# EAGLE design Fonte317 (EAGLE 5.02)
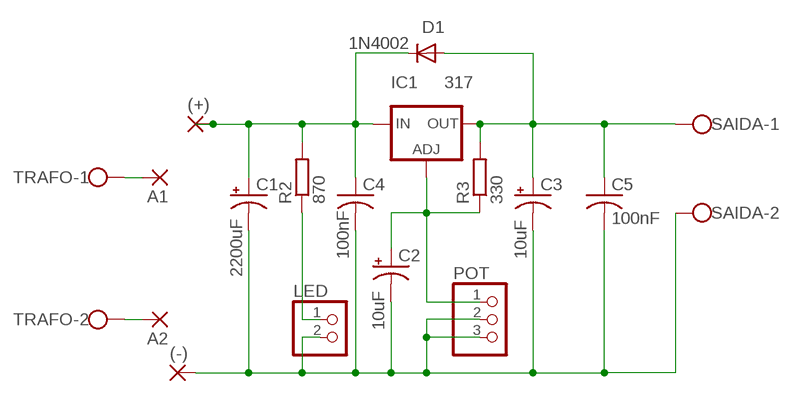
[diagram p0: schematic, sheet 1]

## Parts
(+)  WIREPAD4,16O1,6  [4,16O1,6]
(-)  WIREPAD4,16O1,6  [4,16O1,6]
A1  WIREPAD4,16O1,6  [4,16O1,6]
A2  WIREPAD4,16O1,6  [4,16O1,6]
C1  2200uF  CPOL-USE7.5-18  [E7,5-18]
C2  10uF  CPOL-USE3.5-10  [E3,5-10]
C3  10uF  CPOL-USE3.5-10  [E3,5-10]
C4  100nF  C-US050-035X075  [C050-035X075]
C5  100nF  C-US050-035X075  [C050-035X075]
D1  1N4002  1N4942  [DO41-10]
IC1  317  LM317TS  [317TS]
LED  PINHD-1X2  [1X02]
POT  PINHD-1X3  [1X03]
R2  870  R-EU_0411/3V  [0411V]
R3  330  R-EU_0411/3V  [0411V]
SAIDA  W237-02P  [W237-132]
TRAFO  W237-02P  [W237-132]

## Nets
(+): (+).1(P) C1.+ C4.1 D1.C IC1.3(IN) R2.2
GND: (-).1(P) C1.- C2.- C3.- C4.2 C5.2 LED.2 POT.2 POT.3 SAIDA.2
N$2: LED.1 R2.1
N$3: C2.+ IC1.1(ADJ) POT.1 R3.1
N$4: A2.1(P) TRAFO.2
N$5: A1.1(P) TRAFO.1
N$7: C3.+ C5.1 D1.A IC1.2(OUT) R3.2 SAIDA.1

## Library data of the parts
(+) (-) A1 A2 = wirepad:WIREPAD: Wire PAD connect wire on PCB
C1-C3 = rcl:CPOL-US: POLARIZED CAPACITOR, American symbol
C4 C5 = rcl:C-US: CAPACITOR, American symbol
D1 = diode:1N4942: DIODE
IC1 = v-reg:LM317TS: VOLTAGE REGULATOR
LED = pinhead:PINHD-1X2: PIN HEADER
POT = pinhead:PINHD-1X3: PIN HEADER
R2 R3 = resistor:R-EU_: RESISTOR, European symbol
SAIDA TRAFO = con-wago-508:W237-02P: WAGO SREW CLAMP

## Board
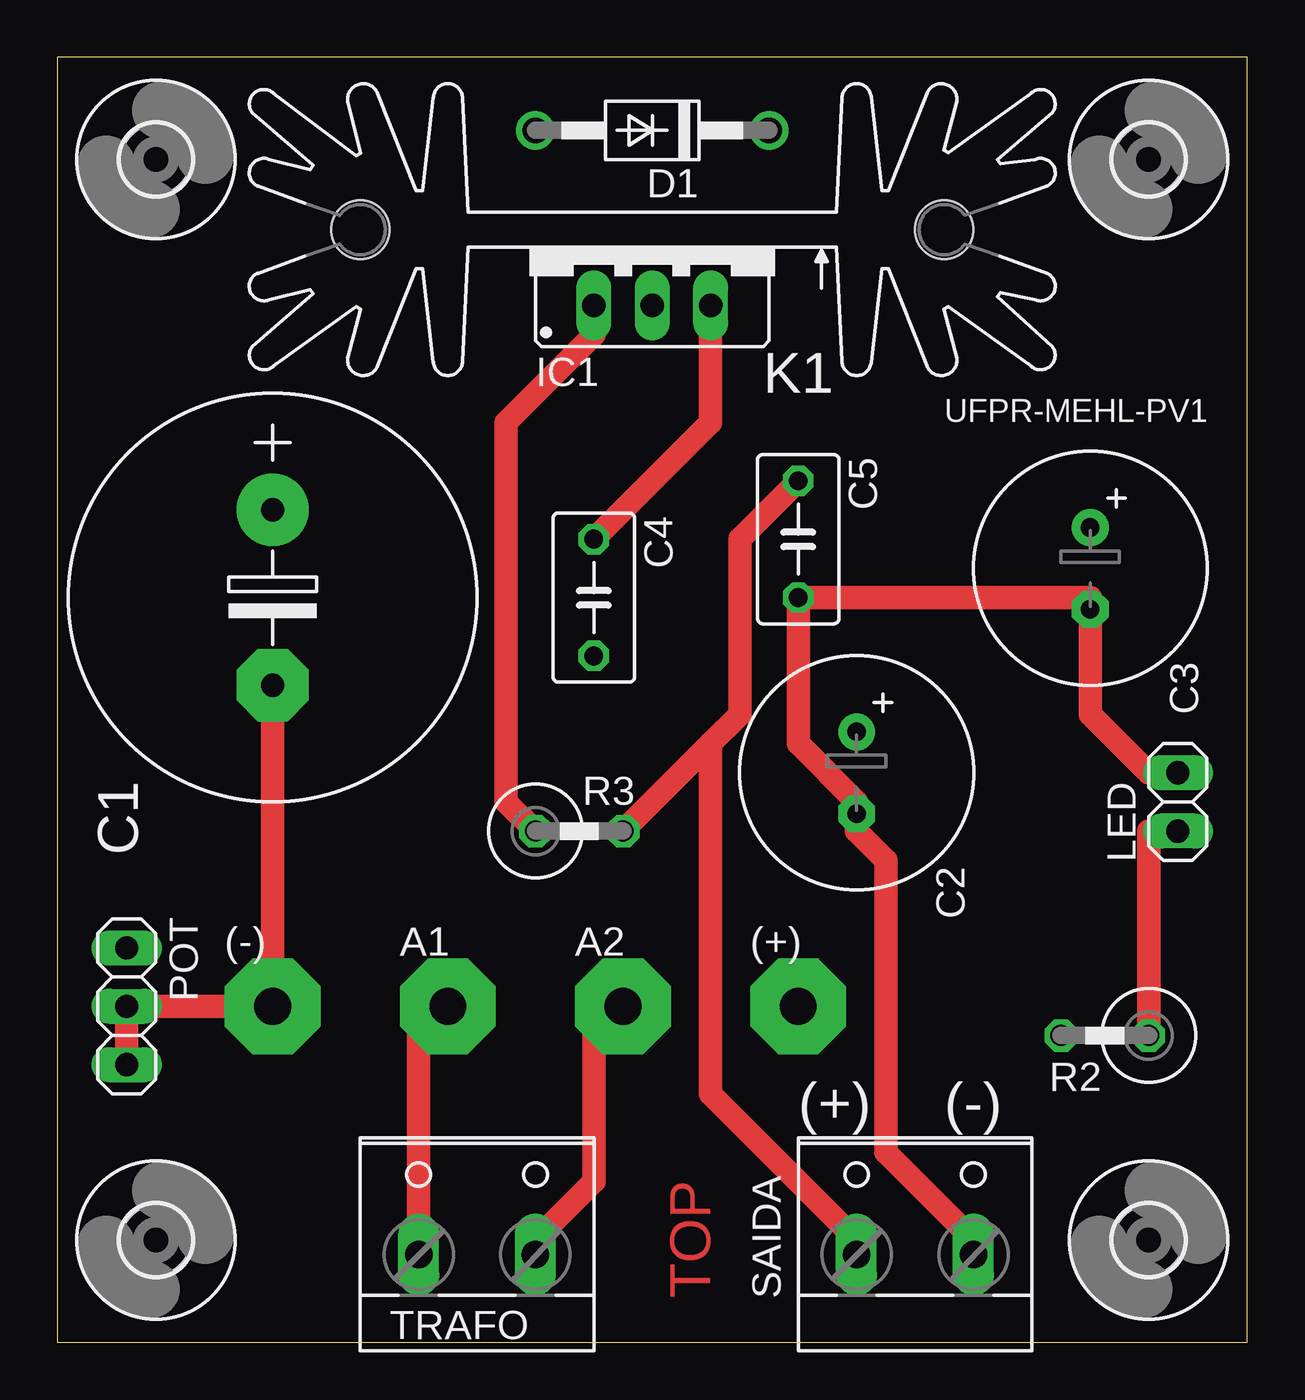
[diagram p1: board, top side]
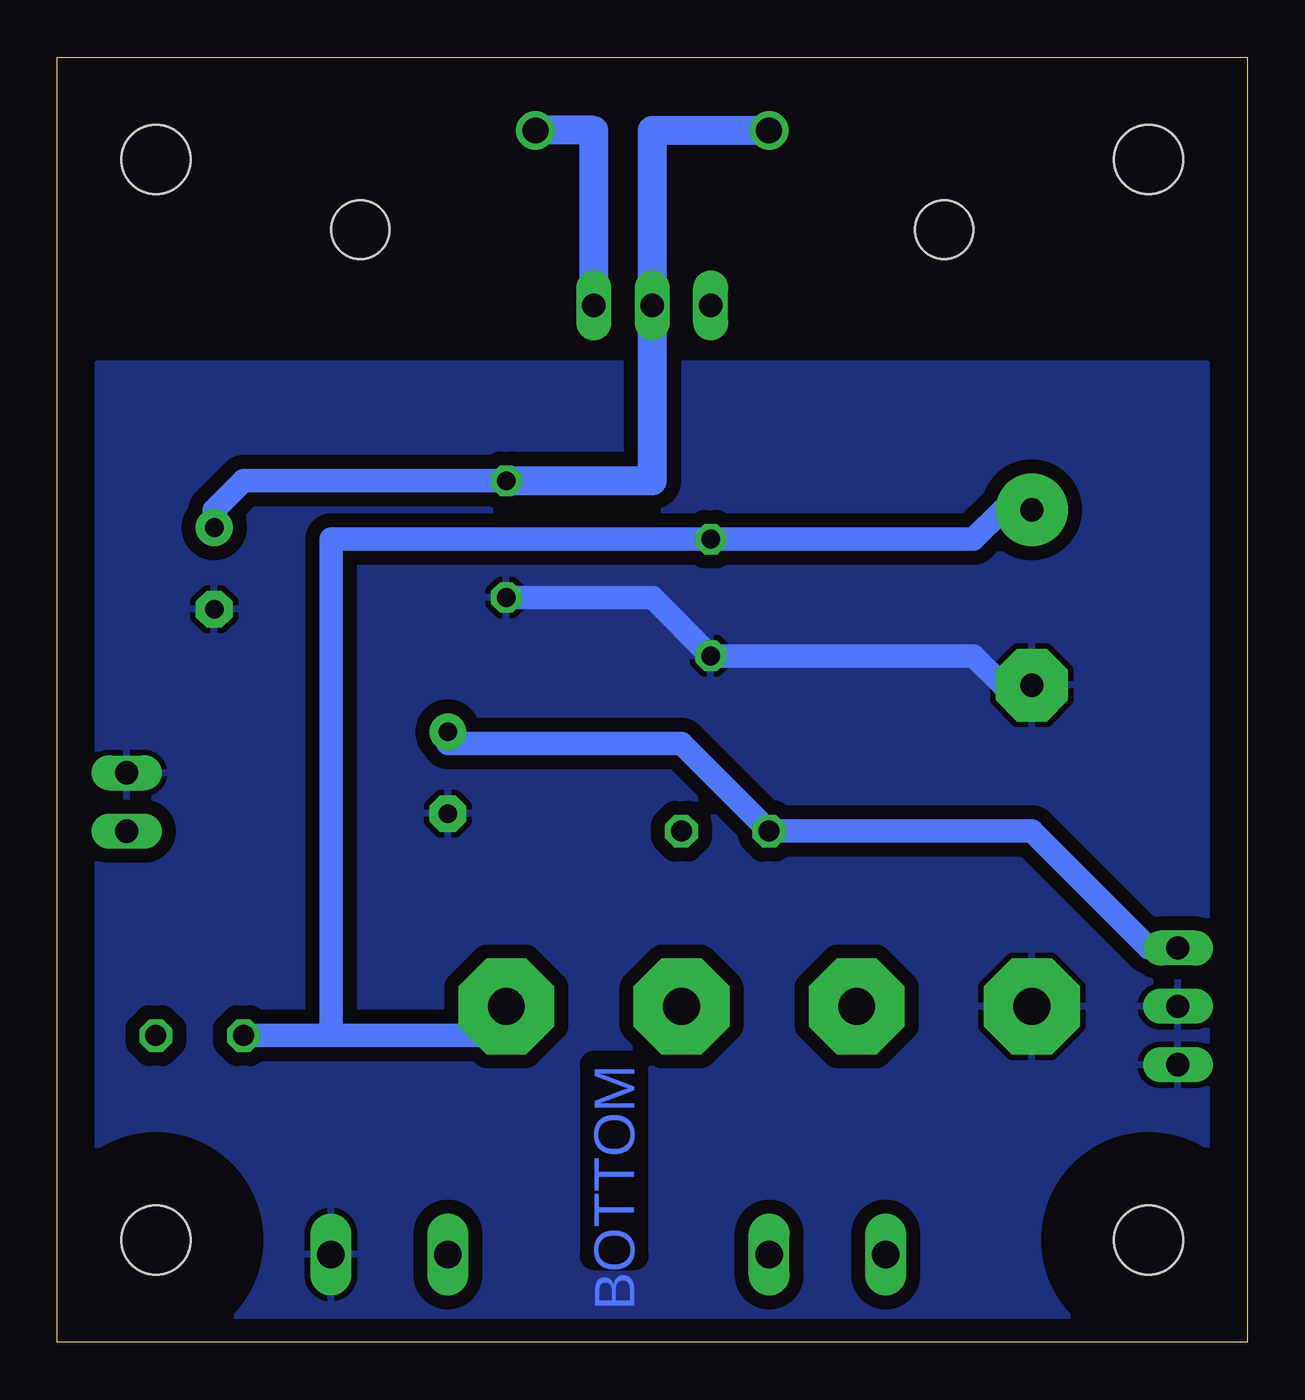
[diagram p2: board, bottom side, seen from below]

Size 51.74 x 55.87 mm. Coordinates in mm from the lower left corner, seen from the top.
Outline: 0,0 51.74,0 51.74,55.87 0,55.87 0,0
Copper layers (1*16): Top 0.035mm / dielectric 1.5mm / Bottom 0.035mm
Design rules "default *": minimum track width 40mil, minimum drill 24mil, track to track 8mil, track to pad 8mil, pad to pad 8mil, via to via 8mil, smd to smd 8mil, copper to edge 40mil, drill to drill 8mil, minimum pad ring 10mil, minimum via ring 8mil, stop-mask expansion 4mil, vias tented up to drill 0mil, thermal gap 10mil

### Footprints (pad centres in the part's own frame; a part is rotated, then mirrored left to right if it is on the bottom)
4,16O1,6 = drill 1.6 pad 4.166 octagon: 1 0,0
E7,5-18 = drill 1.016 pad 3.15 round: + -3.81,0 | drill 1.016 pad 3.15 octagon: - 3.81,0
E3,5-10 = drill 0.813 pad 1.6 round: + -1.778,0 | drill 0.813 pad 1.6 octagon: - 1.778,0
C050-035X075 = drill 0.813 octagon: 1 -2.54,0; 2 2.54,0
DO41-10 = drill 1.118 round: A 5.08,0; C -5.08,0
317TS = drill 1.016 long: 1 -2.54,-2.54; 2 0,-2.54; 3 2.54,-2.54
SK104 = hole 2.54: -12.7,-0.762; 12.7,-0.762
1X02 = drill 1.016 long: 1 -1.27,0; 2 1.27,0
1X03 = drill 1.016 long: 1 -2.54,0; 2 0,0; 3 2.54,0
0411V = drill 0.914 octagon: 1 -2.54,0; 2 1.27,0
W237-132 = drill 1.194 long: 1 -2.54,-0.635; 2 2.54,-0.635
3,0 = hole 3: 0,0

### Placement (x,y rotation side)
(+)  32.22,14.6 0 top
(-)  9.36,14.6 0 top
A1  16.98,14.6 0 top
A2  24.6,14.6 0 top
C1  9.36,32.38 270 top
C2  34.76,24.76 270 top
C3  44.92,33.65 270 top
C4  23.33,32.38 270 top
C5  32.22,34.92 270 top
D1  25.87,52.7 180 top
IC1  25.87,47.62 0 top
K1  [SK104]  25.87,47.62 180 top
LED  48.73,23.49 90 top
POT  3.01,14.6 270 top
R2  44.92,13.33 180 top
R3  23.33,22.22 0 top
SAIDA  37.3,4.44 0 top
TRAFO  18.25,4.44 0 top
U$2  [3,0]  47.46,51.43 0 top
U$3  [3,0]  4.28,51.43 0 top
U$4  [3,0]  4.28,4.44 0 top
U$5  [3,0]  47.46,4.44 0 top

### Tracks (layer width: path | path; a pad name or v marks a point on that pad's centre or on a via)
(+)
  Top 1.016: C4.1 28.41,40 IC1.3
  Bottom 1.016: 39.84,13.33 33.49,13.33 (+).1 | 39.84,13.33 R2.2 | C1.+ 10.63,36.19 11.9,34.92 C4.1 39.84,34.92 39.84,13.33
  Bottom 1.27: D1.C 28.41,52.7 IC1.3
GND
  Top 1.016: POT.3 POT.2 (-).1 C1.- | LED.2 47.46,24.76 44.92,27.3 C3.- 44.92,32.38 C5.2 32.22,26.03 34.76,23.49 C2.- 34.76,22.22 36.03,20.95 36.03,8.25 39.84,4.44 SAIDA.2
  Bottom 1.016: C5.2 25.87,32.38 C4.2 11.9,29.84 10.63,28.57 C1.-
  pour Bottom (isolate 0.61): 1.74,42.54 50,42.54 50,0.63 1.74,0.63
N$2
  Top 1.016: R2.1 47.46,22.22 LED.1
N$3
  Top 1.016: R3.1 19.52,23.49 19.52,40 23.33,43.81 IC1.1
  Bottom 1.016: C2.+ 34.76,26.03 24.6,26.03 R3.1 9.36,22.22 4.28,17.14 POT.1
N$4
  Top 1.016: TRAFO.2 20.79,4.44 23.33,6.98 23.33,13.33 A2.1
N$5
  Top 1.016: TRAFO.1 15.71,13.33 A1.1
N$7
  Top 1.016: 28.41,26.03 29.68,27.3 29.68,34.92 C5.1 | 28.41,26.03 R3.2 | 28.41,26.03 28.41,10.79 34.76,4.44 SAIDA.1
  Bottom 1.016: C5.1 43.65,37.46 44.92,36.19 C3.+
  Bottom 1.27: D1.A 25.87,52.7 IC1.2 25.87,37.46 C5.1

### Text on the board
Top: TOP
Bottom: BOTTOM
tNames: UFPR-MEHL-PV1 | (+) | (-)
